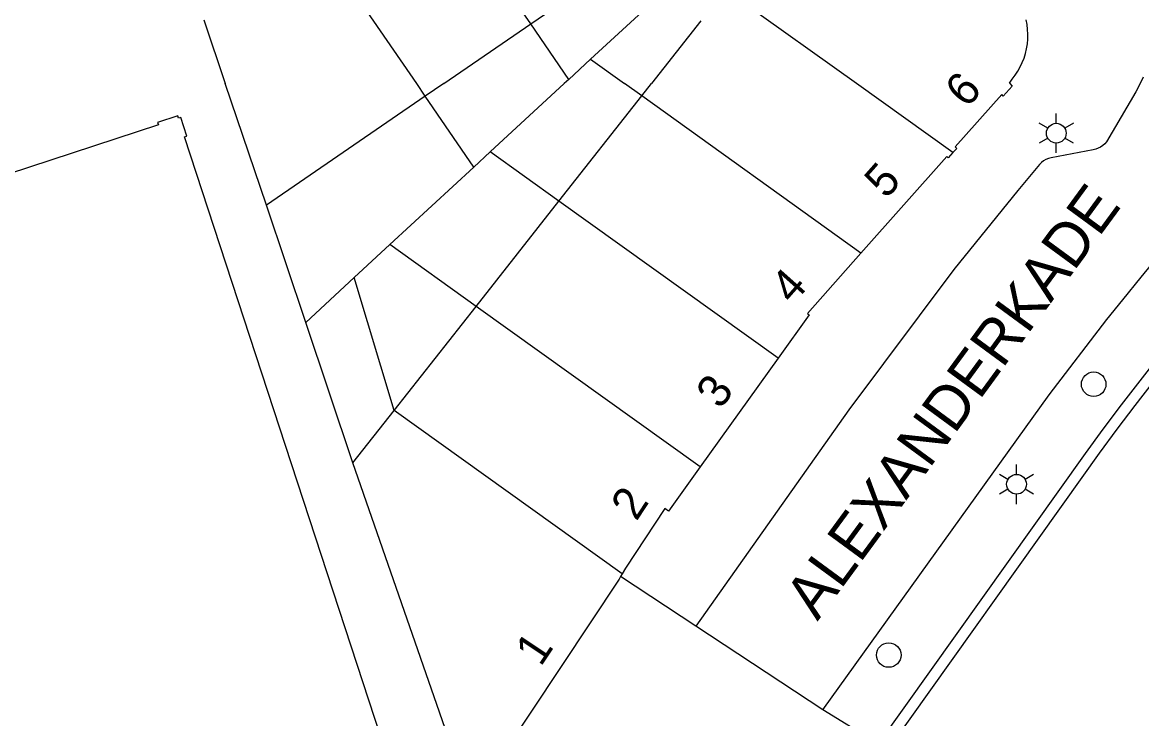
# Model space of a CAD drawing. Extents: x 122462 to 123306, y 485548 to 486417.
# Drawn here: x 123082 to 123133.1, y 486221.1 to 486252.8 of the extents above; entities that cross this region are included whole.
import ezdxf

# ---------------------------------------------------------------- set-up
doc = ezdxf.new("R2010")
doc.units = 0
for name, color, linetype in [('Level 1', 7, 'Continuous'), ('Level 15', 7, 'Continuous'), ('Level 17', 7, 'Continuous'), ('Level 19', 7, 'Continuous'), ('Level 2', 7, 'Continuous'), ('Level 23', 7, 'Continuous'), ('Level 4', 7, 'Continuous'), ('Level 50', 7, 'Continuous'), ('Level 53', 7, 'Continuous'), ('Level 58', 7, 'Continuous'), ('Level 59', 7, 'Continuous')]:
    doc.layers.add(name, color=color, linetype=linetype)

msp = doc.modelspace()

# ---------------------------------------------------------------- linework, layer by layer
at = {"layer": 'Level 1'}
for p, q in [((123105.187, 486252.722), (123109.999, 486256.021)), ((123090.267, 486252.909), (123091.252, 486250)), ((123101.215, 486250), (123105.187, 486252.722)), ((123112.941, 486252.859), (123110.689, 486250)), ((123093.129, 486244.457), (123091.252, 486250)), ((123101.215, 486250), (123100.376, 486249.425)), ((123110.245, 486249.437), (123110.689, 486250)), ((123100.376, 486249.425), (123093.129, 486244.457)), ((123106.467, 486244.642), (123110.245, 486249.437)), ((123102.689, 486239.848), (123106.467, 486244.642)), ((123098.954, 486235.108), (123102.689, 486239.848)), ((123116.465, 486237.484), (123112.916, 486232.526)), ((123097.066, 486232.712), (123098.954, 486235.108)), ((123102.186, 486218.038), (123097.066, 486232.712)), ((123109.361, 486227.657), (123109.285, 486227.53))]:
    msp.add_line(p, q, dxfattribs=at)
for points in [[(123127.042, 486250), (123127.025, 486250.017), (123127.147, 486250.206), (123127.282, 486250.381), (123127.404, 486250.566), (123127.513, 486250.759), (123127.608, 486250.958), (123127.689, 486251.165), (123127.754, 486251.376), (123127.805, 486251.592), (123127.84, 486251.81), (123127.859, 486252.031), (123127.863, 486252.252), (123127.851, 486252.473), (123127.823, 486252.693), (123127.779, 486252.91)], [(123127.042, 486250), (123127.15, 486249.89), (123126.741, 486249.431), (123126.667, 486249.497), (123124.547, 486247.118), (123124.62, 486247.049), (123124.445, 486246.853)], [(123124.445, 486246.853), (123124.232, 486246.613), (123124.158, 486246.68), (123120.247, 486242.275)], [(123120.247, 486242.275), (123117.807, 486239.528), (123117.88, 486239.459), (123116.465, 486237.484)], [(123112.916, 486232.526), (123111.473, 486230.511), (123111.304, 486230.632), (123109.509, 486227.91), (123109.361, 486227.657)], [(123109.285, 486227.53), (123109.219, 486227.42), (123103.891, 486219.401), (123103.969, 486219.35), (123103.62, 486218.88), (123103.193, 486219.185), (123102.38, 486218.039), (123102.32, 486218.084), (123102.186, 486218.038)]]:
    msp.add_lwpolyline(points, dxfattribs=at)
at = {"layer": 'Level 15'}
for points in [[(123121.044, 486219.902), (123130.483, 486233.136), (123131.303, 486234.253), (123132.135, 486235.36), (123132.98, 486236.457), (123133.838, 486237.545), (123134.708, 486238.622), (123135.59, 486239.69), (123136.485, 486240.748), (123137.391, 486241.795), (123138.31, 486242.831), (123139.241, 486243.857), (123140.183, 486244.872), (123141.137, 486245.877), (123142.102, 486246.87), (123143.079, 486247.852), (123144.067, 486248.823), (123145.066, 486249.782), (123145.298, 486250)], [(123146.028, 486250), (123145.494, 486249.5), (123144.51, 486248.557), (123143.537, 486247.603), (123142.575, 486246.638), (123141.624, 486245.663), (123140.684, 486244.676), (123139.756, 486243.679), (123138.838, 486242.672), (123137.933, 486241.654), (123137.038, 486240.626), (123136.156, 486239.587), (123135.285, 486238.539), (123134.427, 486237.481), (123133.58, 486236.414), (123132.746, 486235.336), (123131.924, 486234.25), (123131.114, 486233.154), (123130.317, 486232.049), (123121.451, 486219.611)]]:
    msp.add_lwpolyline(points, dxfattribs=at)
at = {"layer": 'Level 17'}
for points in [[(123132.985, 486250), (123132.985, 486249.999), (123132.789, 486249.619), (123131.445, 486247.347), (123131.366, 486247.258), (123131.277, 486247.179), (123131.179, 486247.111), (123131.074, 486247.055), (123130.962, 486247.012), (123130.847, 486246.983), (123128.924, 486246.614), (123128.803, 486246.583), (123128.687, 486246.536), (123128.577, 486246.476), (123128.476, 486246.402), (123128.385, 486246.316), (123127.407, 486245.121), (123124.481, 486241.531), (123119.691, 486235.131), (123112.719, 486225.271)], [(123118.511, 486221.461), (123128.829, 486235.821), (123131.462, 486239.244), (123132.188, 486240.152), (123133.024, 486241.177), (123133.869, 486242.193), (123134.726, 486243.2), (123135.592, 486244.198), (123136.469, 486245.188), (123137.356, 486246.168), (123138.253, 486247.14), (123139.159, 486248.102), (123140.076, 486249.055), (123141.002, 486249.998), (123141.004, 486250)], [(123133.12, 486250.297), (123132.985, 486250)]]:
    msp.add_lwpolyline(points, dxfattribs=at)
at = {"layer": 'Level 19'}
for p, q in [((123106.919, 486250.195), (123105.187, 486252.722)), ((123107.907, 486251.108), (123106.919, 486250.195)), ((123107.907, 486251.108), (123109.457, 486250)), ((123106.708, 486250), (123103.334, 486246.885)), ((123106.919, 486250.195), (123106.708, 486250)), ((123110.245, 486249.437), (123109.457, 486250)), ((123102.589, 486246.197), (123100.376, 486249.425)), ((123103.334, 486246.885), (123102.589, 486246.197)), ((123106.467, 486244.642), (123103.334, 486246.885)), ((123098.761, 486242.66), (123102.589, 486246.197)), ((123094.92, 486239.113), (123093.129, 486244.457)), ((123098.761, 486242.66), (123097.134, 486241.158)), ((123102.689, 486239.848), (123098.761, 486242.66)), ((123097.134, 486241.158), (123094.92, 486239.113)), ((123098.954, 486235.108), (123097.134, 486241.158)), ((123097.066, 486232.712), (123094.92, 486239.113))]:
    msp.add_line(p, q, dxfattribs=at)
msp.add_lwpolyline([(123107.907, 486251.108), (123111.194, 486254.144), (123111.256, 486254.187)], dxfattribs=at)
at = {"layer": 'Level 2'}
msp.add_lwpolyline([(123105.234, 486197.313), (123103.817, 486206.594), (123095.897, 486205.385), (123095.505, 486206.603), (123101.179, 486208.427), (123101.212, 486208.327), (123102.143, 486208.631), (123102.112, 486208.726), (123102.207, 486208.757), (123101.972, 486209.491), (123101.872, 486209.459), (123089.397, 486247.567), (123089.503, 486247.602), (123089.223, 486248.457), (123089.118, 486248.423), (123089.084, 486248.526), (123088.164, 486248.225), (123088.198, 486248.122), (123070.539, 486242.34)], dxfattribs=at)
at = {"layer": 'Level 23'}
for p, q in [((123112.719, 486225.271), (123109.285, 486227.53)), ((123118.511, 486221.461), (123112.719, 486225.271)), ((123120.837, 486220.029), (123118.511, 486221.461))]:
    msp.add_line(p, q, dxfattribs=at)
at = {"layer": 'Level 4'}
for p, q in [((123105.187, 486252.722), (123097.883, 486263.376)), ((123099.982, 486250), (123093.111, 486260.017)), ((123120.048, 486250), (123114.713, 486253.818)), ((123100.376, 486249.425), (123099.982, 486250)), ((123124.445, 486246.853), (123120.048, 486250)), ((123120.247, 486242.275), (123110.245, 486249.437)), ((123116.465, 486237.484), (123106.467, 486244.642)), ((123112.916, 486232.526), (123102.689, 486239.848)), ((123109.361, 486227.657), (123098.954, 486235.108))]:
    msp.add_line(p, q, dxfattribs=at)
at = {"layer": 'Level 50'}
for p, q in [((123129.159, 486248.19), (123129.159, 486248.64)), ((123128.769, 486247.965), (123128.379, 486248.19)), ((123129.938, 486248.19), (123129.548, 486247.965)), ((123128.769, 486247.515), (123128.379, 486247.29)), ((123129.938, 486247.29), (123129.548, 486247.515)), ((123129.159, 486246.84), (123129.159, 486247.29)), ((123127.344, 486232.187), (123127.344, 486232.637)), ((123126.954, 486231.962), (123126.564, 486232.187)), ((123128.123, 486232.187), (123127.733, 486231.962)), ((123126.954, 486231.512), (123126.564, 486231.287)), ((123127.344, 486230.837), (123127.344, 486231.287)), ((123128.123, 486231.287), (123127.733, 486231.512))]:
    msp.add_line(p, q, dxfattribs=at)
for centre in [(123129.159, 486247.74), (123127.344, 486231.737)]:
    msp.add_circle(centre, 0.45, dxfattribs=at)
at = {"layer": 'Level 53'}
for centre in [(123130.864, 486236.299), (123121.516, 486223.954)]:
    msp.add_circle(centre, 0.56, dxfattribs=at)

# ---------------------------------------------------------------- texts
at = {"layer": 'Level 58'}
for s, rotation, p in [('6', 48.2948, (123125.082, 486248.845)), ('5', 48.4156, (123121.403, 486244.705)), ('4', 48.4025, (123117.126, 486239.889)), ('3', 54.3775, (123113.847, 486235.115)), ('2', 56.6035, (123110.002, 486230.019)), ('1', 56.3754, (123105.64, 486223.388))]:
    msp.add_text(s, height=1.5, rotation=rotation, dxfattribs=at).set_placement(p)
at = {"layer": 'Level 59'}
for s, rotation, p in [('ALEXANDERPLEIN', 304.8963, (123124.344, 486270.233)), ('ALEXANDERKADE', 53.7443, (123118.265, 486225.472))]:
    msp.add_text(s, height=2, rotation=rotation, dxfattribs=at).set_placement(p)

doc.saveas('drawing.dxf')
